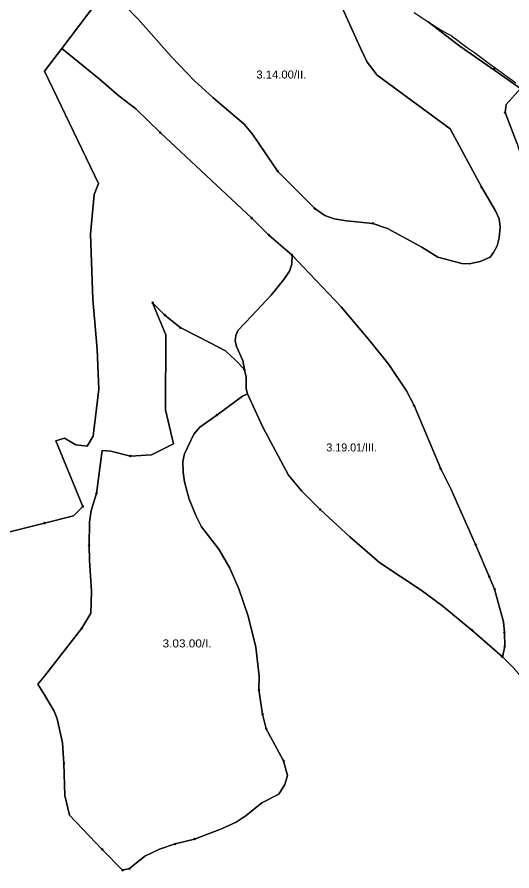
# Model space of a CAD drawing. Extents: x -650455 to -642254, y -1075222 to -1066610.
# Drawn here: x -645034 to -644416, y -1073102 to -1072036 of the extents above; entities that cross this region are included whole.
import ezdxf
from ezdxf.enums import TextEntityAlignment as Align

# ---------------------------------------------------------------- set-up
doc = ezdxf.new("R2010")
doc.units = 0
doc.header["$LTSCALE"] = 4
doc.header["$PDMODE"] = 32
doc.header["$PDSIZE"] = 2
for name, color, linetype, lineweight in [('1', 7, 'Continuous', 25), ('11', 7, 'Continuous', 13), ('12', 7, 'Continuous', 13), ('13', 7, 'Continuous', 13), ('14', 7, 'Continuous', 13)]:
    doc.layers.add(name, color=color, linetype=linetype, lineweight=lineweight)
doc.layers.add('2', color=7, linetype='Continuous')

msp = doc.modelspace()

# ---------------------------------------------------------------- linework, layer by layer
at = {"layer": '1'}
for points in [[(-644841.196, -1072085.989), (-644882.287, -1072039.303), (-644920.668, -1072000), (-644846.005, -1071899.418), (-644841.808, -1071890.5), (-644840.584, -1071879.659), (-644841.109, -1071869.867), (-644842.508, -1071858.851), (-644848.802, -1071841.89), (-644852.999, -1071832.972), (-644858.507, -1071824.054), (-644814.968, -1071847.135), (-644781.395, -1071868.992)], [(-644431.857, -1072311.904), (-644430.633, -1072298.615), (-644431.682, -1072288.473), (-644436.403, -1072278.331), (-644453.627, -1072249.305), (-644492.882, -1072176.04), (-644584.42, -1072108.721), (-644596.572, -1072092.634), (-644604.965, -1072074.973), (-644630.931, -1072017.97), (-644644.606, -1072000), (-644652.089, -1071990.168), (-644682.776, -1071960.792), (-644705.508, -1071942.607), (-644747.386, -1071912.357), (-644761.374, -1071900.641), (-644769.942, -1071891.374), (-644776.237, -1071882.107), (-644781.395, -1071868.992), (-644763.822, -1071881.057), (-644761.199, -1071879.659), (-644742.849, -1071890.721)], [(-644923.589, -1072003.101), (-644978.202, -1072075.468), (-645000, -1072103.795), (-644932.308, -1072244.028), (-644938, -1072258.001), (-644942.5, -1072307.5), (-644939.5, -1072388.5), (-644934, -1072451.501)], [(-644504.788, -1072600.507), (-644538.098, -1072521.472), (-644547.541, -1072502.937), (-644569.835, -1072470.239), (-644593.265, -1072440.689), (-644629.198, -1072398.199), (-644676.672, -1072348.015), (-644690.563, -1072333.557), (-644719.414, -1072308.552), (-644741.009, -1072287.394), (-644855.103, -1072180.732), (-644885.79, -1072150.832), (-644907.123, -1072134.745), (-644931.428, -1072113.412), (-644978.202, -1072075.468), (-644923.589, -1072003.101)], [(-644920.668, -1072000), (-644882.287, -1072039.303), (-644841.196, -1072085.989), (-644812.607, -1072115.89), (-644789.351, -1072136.698), (-644750.62, -1072169.92), (-644740.129, -1072182.51), (-644708.393, -1072229.022), (-644684.088, -1072253.327), (-644662.318, -1072275.534), (-644649.728, -1072283.927), (-644637.838, -1072288.298), (-644622.451, -1072290.921), (-644589.753, -1072293.893), (-644571.218, -1072300.538), (-644528.64, -1072323.619), (-644508.357, -1072336.209), (-644478.457, -1072343.902), (-644469.539, -1072344.602), (-644455.463, -1072341.629), (-644443.223, -1072336.034), (-644439.026, -1072330.264), (-644434.305, -1072322.045), (-644431.857, -1072311.904)], [(-644630.931, -1072017.97), (-644604.965, -1072074.973), (-644596.572, -1072092.634), (-644584.42, -1072108.721), (-644492.882, -1072176.04), (-644453.627, -1072249.305), (-644436.403, -1072278.331), (-644431.682, -1072288.473), (-644430.633, -1072298.615), (-644431.857, -1072311.904), (-644434.305, -1072322.045), (-644439.026, -1072330.264), (-644443.223, -1072336.034), (-644455.463, -1072341.629), (-644469.539, -1072344.602), (-644478.457, -1072343.902), (-644508.357, -1072336.209), (-644528.64, -1072323.619), (-644571.218, -1072300.538), (-644589.753, -1072293.893), (-644622.451, -1072290.921), (-644637.838, -1072288.298), (-644649.728, -1072283.927), (-644662.318, -1072275.534), (-644684.088, -1072253.327), (-644708.393, -1072229.022), (-644740.129, -1072182.51), (-644750.62, -1072169.92), (-644789.351, -1072136.698), (-644812.607, -1072115.89), (-644841.196, -1072085.989)], [(-644538.207, -1072030.496), (-644520.385, -1072042.196), (-644480.817, -1072072.875), (-644437.149, -1072103.18), (-644405.404, -1072125.733), (-644423.152, -1072145.492), (-644424.551, -1072155.634), (-644409.426, -1072194.802), (-644395.962, -1072238.516), (-644382.411, -1072266.143), (-644377.69, -1072283.279), (-644368.51, -1072344.479), (-644363.526, -1072367.91), (-644357.056, -1072388.717), (-644349.887, -1072398.859), (-644340.095, -1072405.329), (-644329.079, -1072409.525), (-644322.085, -1072408.476), (-644311.769, -1072403.231), (-644304.425, -1072396.061), (-644301.277, -1072389.242), (-644299.529, -1072379.975), (-644298.392, -1072369.308), (-644286.239, -1072437.852)], [(-645051.292, -1072681.171), (-645000, -1072668.218), (-644963.5, -1072659), (-644952, -1072647.5), (-644985.633, -1072565.416), (-644974.792, -1072562.094), (-644960.629, -1072570.487), (-644946.5, -1072572.001), (-644939, -1072559.5), (-644932, -1072501.001), (-644934, -1072451.501), (-644939.5, -1072388.5), (-644942.5, -1072307.5), (-644938, -1072258.001), (-644932.308, -1072244.028), (-645000, -1072103.795), (-644978.202, -1072075.468), (-644931.428, -1072113.412), (-644907.123, -1072134.745), (-644885.79, -1072150.832), (-644855.103, -1072180.732), (-644741.009, -1072287.394), (-644719.414, -1072308.552), (-644690.563, -1072333.557)], [(-644405.404, -1072125.733), (-644437.149, -1072103.18), (-644438.697, -1072098.552), (-644410.923, -1072118.41)], [(-644409.426, -1072194.802), (-644424.551, -1072155.634), (-644423.152, -1072145.492), (-644405.404, -1072125.733)], [(-644690.563, -1072333.557), (-644690.913, -1072344.747), (-644693.885, -1072353.49), (-644700.967, -1072363.982), (-644716.704, -1072383.566), (-644741.009, -1072409.444), (-644758.407, -1072427.629), (-644761.03, -1072433.924), (-644761.555, -1072440.569), (-644759.806, -1072447.563), (-644752.2, -1072465.224), (-644750.102, -1072476.589), (-644761.118, -1072464.699), (-644773.882, -1072453.158), (-644791.892, -1072443.716), (-644830.186, -1072424.132), (-644849.42, -1072408.395), (-644864.72, -1072393.008), (-644848.109, -1072433.225), (-644848.721, -1072526.773), (-644838.492, -1072569.088), (-644866.119, -1072582.902), (-644892.522, -1072584.476), (-644917.177, -1072578.356), (-644927.668, -1072577.656), (-644934.935, -1072631.107), (-644941.579, -1072652.265), (-644943.59, -1072666.953), (-644944.115, -1072695.979), (-644943.415, -1072715.038), (-644941.055, -1072753.157), (-644941.841, -1072780.784), (-644953.207, -1072799.494), (-645000, -1072859.198), (-645008.025, -1072869.436), (-645000, -1072882.662), (-644987.654, -1072903.009), (-644983.807, -1072912.451), (-644977.337, -1072942.526), (-644975.501, -1072968.405)], [(-644968.595, -1073032.752), (-644974.54, -1073008.447), (-644975.501, -1072968.405), (-644977.337, -1072942.526), (-644983.807, -1072912.451), (-644987.654, -1072903.009), (-645000, -1072882.662), (-645008.025, -1072869.436), (-645000, -1072859.198), (-644953.207, -1072799.494), (-644941.841, -1072780.784), (-644941.055, -1072753.157), (-644943.415, -1072715.038), (-644944.115, -1072695.979), (-644943.59, -1072666.953), (-644941.579, -1072652.265), (-644934.935, -1072631.107), (-644927.668, -1072577.656), (-644917.177, -1072578.356), (-644892.522, -1072584.476), (-644866.119, -1072582.902), (-644838.492, -1072569.088), (-644848.721, -1072526.773), (-644848.109, -1072433.225), (-644864.72, -1072393.008), (-644849.42, -1072408.395), (-644830.186, -1072424.132), (-644791.892, -1072443.716), (-644773.882, -1072453.158), (-644761.118, -1072464.699), (-644750.102, -1072476.589)], [(-644934, -1072451.501), (-644932, -1072501.001), (-644939, -1072559.5), (-644946.5, -1072572.001), (-644960.629, -1072570.487), (-644974.792, -1072562.094), (-644985.633, -1072565.416), (-644952, -1072647.5), (-644963.5, -1072659), (-645000, -1072668.218), (-645051.292, -1072681.171)], [(-644750.102, -1072476.589), (-644747.829, -1072486.556), (-644748.004, -1072500.37), (-644746.255, -1072506.665), (-644752.385, -1072509.582), (-644784.471, -1072533.362), (-644805.629, -1072548.4), (-644813.322, -1072556.968), (-644825.037, -1072581.623), (-644827.136, -1072591.24), (-644826.699, -1072604.529), (-644824.775, -1072616.769), (-644819.18, -1072638.101), (-644810.35, -1072659.609), (-644803.53, -1072672.723), (-644782.198, -1072700.525), (-644768.122, -1072724.481), (-644757.106, -1072750.184), (-644745.478, -1072784.281), (-644736.036, -1072822.925), (-644731.752, -1072859.47), (-644731.926, -1072876.256), (-644727.468, -1072906.856), (-644722.921, -1072924.866), (-644701.152, -1072965.083), (-644696.256, -1072983.443), (-644699.753, -1072994.634), (-644707.097, -1073006.699), (-644728.342, -1073017.54), (-644747.926, -1073033.102), (-644760.341, -1073041.67), (-644778.7, -1073050.063), (-644812.273, -1073062.653), (-644836.491, -1073068.773), (-644856.074, -1073075.417), (-644874.609, -1073083.985), (-644893.669, -1073099.547), (-644902.412, -1073101.471), (-644927.591, -1073075.592), (-644968.595, -1073032.752)], [(-644975.501, -1072968.405), (-644974.54, -1073008.447), (-644968.595, -1073032.752), (-644927.591, -1073075.592), (-644902.412, -1073101.471), (-644893.669, -1073099.547), (-644874.609, -1073083.985), (-644856.074, -1073075.417), (-644836.491, -1073068.773), (-644812.273, -1073062.653), (-644778.7, -1073050.063), (-644760.341, -1073041.67), (-644747.926, -1073033.102), (-644728.342, -1073017.54), (-644707.097, -1073006.699), (-644699.753, -1072994.634), (-644696.256, -1072983.443), (-644701.152, -1072965.083), (-644722.921, -1072924.866), (-644727.468, -1072906.856), (-644731.926, -1072876.256), (-644731.752, -1072859.47), (-644736.036, -1072822.925), (-644745.478, -1072784.281), (-644757.106, -1072750.184), (-644768.122, -1072724.481), (-644782.198, -1072700.525), (-644803.53, -1072672.723), (-644810.35, -1072659.609), (-644819.18, -1072638.101), (-644824.775, -1072616.769), (-644826.699, -1072604.529), (-644827.136, -1072591.24), (-644825.037, -1072581.623), (-644813.322, -1072556.968), (-644805.629, -1072548.4), (-644784.471, -1072533.362), (-644752.385, -1072509.582), (-644746.255, -1072506.665), (-644727.03, -1072548.225)], [(-644727.03, -1072548.225), (-644695.119, -1072608.201), (-644678.508, -1072628.484), (-644655.514, -1072651.216), (-644618.27, -1072685.138), (-644580.763, -1072717.661), (-644529.268, -1072751.758), (-644502.165, -1072771.867), (-644465.97, -1072801.767), (-644427.764, -1072835.165), (-644413.997, -1072848.687)], [(-644413.997, -1072848.687), (-644427.764, -1072835.165), (-644424.966, -1072822.225), (-644425.316, -1072804.914), (-644426.54, -1072791.45), (-644437.556, -1072750.534), (-644444.375, -1072734.797), (-644461.249, -1072695.105), (-644492.286, -1072625.512), (-644504.788, -1072600.507)]]:
    msp.add_lwpolyline(points, dxfattribs=at)
for points in [[(-644438.697, -1072098.552), (-644437.149, -1072103.18), (-644480.817, -1072072.875), (-644520.385, -1072042.196), (-644505.751, -1072051.804), (-644497.002, -1072057.025), (-644493.333, -1072058.718), (-644492.204, -1072058.859), (-644491.922, -1072059.566), (-644471.32, -1072074.806), (-644462.853, -1072080.592), (-644441.121, -1072096.818)], [(-644427.764, -1072835.165), (-644465.97, -1072801.767), (-644502.165, -1072771.867), (-644529.268, -1072751.758), (-644580.763, -1072717.661), (-644618.27, -1072685.138), (-644655.514, -1072651.216), (-644678.508, -1072628.484), (-644695.119, -1072608.201), (-644727.03, -1072548.225), (-644746.255, -1072506.665), (-644748.004, -1072500.37), (-644747.829, -1072486.556), (-644750.102, -1072476.589), (-644752.2, -1072465.224), (-644759.806, -1072447.563), (-644761.555, -1072440.569), (-644761.03, -1072433.924), (-644758.407, -1072427.629), (-644741.009, -1072409.444), (-644716.704, -1072383.566), (-644700.967, -1072363.982), (-644693.885, -1072353.49), (-644690.913, -1072344.747), (-644690.563, -1072333.557), (-644676.672, -1072348.015), (-644629.198, -1072398.199), (-644593.265, -1072440.689), (-644569.835, -1072470.239), (-644547.541, -1072502.937), (-644538.098, -1072521.472), (-644504.788, -1072600.507), (-644492.286, -1072625.512), (-644461.249, -1072695.105), (-644444.375, -1072734.797), (-644437.556, -1072750.534), (-644426.54, -1072791.45), (-644425.316, -1072804.914), (-644424.966, -1072822.225)]]:
    msp.add_lwpolyline(points, close=True, dxfattribs=at)
at = {"layer": '11'}
for p, q in [((-644727.468, -1072906.856), (-644731.926, -1072876.256)), ((-644722.921, -1072924.866), (-644727.468, -1072906.856)), ((-644968.595, -1073032.752), (-644927.591, -1073075.592)), ((-644927.591, -1073075.592), (-644902.412, -1073101.471))]:
    msp.add_line(p, q, dxfattribs=at)
for points in [[(-645000, -1072668.218), (-644963.5, -1072659), (-644952, -1072647.5), (-644985.633, -1072565.416), (-644974.792, -1072562.094), (-644960.629, -1072570.487), (-644946.5, -1072572.001), (-644939, -1072559.5), (-644932, -1072501.001), (-644934, -1072451.501), (-644939.5, -1072388.5), (-644942.5, -1072307.5), (-644938, -1072258.001), (-644932.308, -1072244.028), (-645000, -1072103.795), (-644978.202, -1072075.468), (-644923.589, -1072003.101), (-644924, -1072000)], [(-644410.923, -1072118.41), (-644438.697, -1072098.552), (-644437.149, -1072103.18), (-644405.404, -1072125.733)], [(-645232, -1072393.5), (-645239, -1072447.501), (-645252.5, -1072519.501), (-645249.5, -1072546.5), (-645229.5, -1072578), (-645192.5, -1072623), (-645125, -1072686.501), (-645107.317, -1072702.887), (-645051.292, -1072681.171), (-645000, -1072668.218)], [(-644864.72, -1072393.008), (-644848.109, -1072433.225), (-644848.721, -1072526.773), (-644838.492, -1072569.088), (-644866.119, -1072582.902), (-644892.522, -1072584.476), (-644917.177, -1072578.356), (-644927.668, -1072577.656), (-644934.935, -1072631.107), (-644941.579, -1072652.265), (-644943.59, -1072666.953), (-644944.115, -1072695.979), (-644943.415, -1072715.038), (-644941.055, -1072753.157), (-644941.841, -1072780.784), (-644953.207, -1072799.494), (-645000, -1072859.198), (-645008.025, -1072869.436), (-645000, -1072882.662), (-644987.654, -1072903.009), (-644983.807, -1072912.451), (-644977.337, -1072942.526), (-644975.501, -1072968.405), (-644974.54, -1073008.447), (-644968.595, -1073032.752)], [(-644731.926, -1072876.256), (-644731.752, -1072859.47), (-644736.036, -1072822.925), (-644745.478, -1072784.281), (-644757.106, -1072750.184), (-644768.122, -1072724.481), (-644782.198, -1072700.525), (-644803.53, -1072672.723), (-644810.35, -1072659.609), (-644819.18, -1072638.101), (-644824.775, -1072616.769), (-644826.699, -1072604.529), (-644827.136, -1072591.24), (-644825.037, -1072581.623), (-644813.322, -1072556.968), (-644805.629, -1072548.4), (-644784.471, -1072533.362), (-644752.385, -1072509.582), (-644746.255, -1072506.665), (-644748.004, -1072500.37), (-644747.829, -1072486.556), (-644750.102, -1072476.589), (-644761.118, -1072464.699), (-644773.882, -1072453.158), (-644791.892, -1072443.716), (-644830.186, -1072424.132), (-644849.42, -1072408.395), (-644864.72, -1072393.008)], [(-644812.273, -1073062.653), (-644778.7, -1073050.063), (-644760.341, -1073041.67), (-644747.926, -1073033.102), (-644728.342, -1073017.54), (-644707.097, -1073006.699), (-644699.753, -1072994.634), (-644696.256, -1072983.443), (-644701.152, -1072965.083), (-644722.921, -1072924.866)], [(-644902.412, -1073101.471), (-644893.669, -1073099.547), (-644874.609, -1073083.985), (-644856.074, -1073075.417), (-644836.491, -1073068.773), (-644812.273, -1073062.653)]]:
    msp.add_lwpolyline(points, dxfattribs=at)
for p in [(-644864.72, -1072393.008), (-645000, -1072668.218), (-644731.926, -1072876.256), (-644727.468, -1072906.856), (-644722.921, -1072924.866), (-644812.273, -1073062.653), (-644927.591, -1073075.592), (-644902.412, -1073101.471)]:
    msp.add_point(p, dxfattribs=at)
at = {"layer": '12'}
for points in [[(-644920.668, -1072000), (-644882.287, -1072039.303), (-644841.196, -1072085.989), (-644812.607, -1072115.89), (-644789.351, -1072136.698), (-644750.62, -1072169.92), (-644740.129, -1072182.51), (-644708.393, -1072229.022)], [(-644453.627, -1072249.305), (-644492.882, -1072176.04), (-644584.42, -1072108.721), (-644596.572, -1072092.634), (-644604.965, -1072074.973), (-644630.931, -1072017.97)], [(-644708.393, -1072229.022), (-644684.088, -1072253.327), (-644662.318, -1072275.534), (-644649.728, -1072283.927), (-644637.838, -1072288.298), (-644622.451, -1072290.921), (-644589.753, -1072293.893)], [(-644589.753, -1072293.893), (-644571.218, -1072300.538), (-644528.64, -1072323.619), (-644508.357, -1072336.209), (-644478.457, -1072343.902), (-644469.539, -1072344.602), (-644455.463, -1072341.629), (-644443.223, -1072336.034), (-644439.026, -1072330.264), (-644434.305, -1072322.045), (-644431.857, -1072311.904), (-644430.633, -1072298.615), (-644431.682, -1072288.473), (-644436.403, -1072278.331), (-644453.627, -1072249.305)]]:
    msp.add_lwpolyline(points, dxfattribs=at)
for p in [(-644708.393, -1072229.022), (-644453.627, -1072249.305), (-644589.753, -1072293.893)]:
    msp.add_point(p, dxfattribs=at)
at = {"layer": '13'}
for p, q in [((-644741.009, -1072287.394), (-644855.103, -1072180.732)), ((-644849.42, -1072408.395), (-644830.186, -1072424.132)), ((-644444.375, -1072734.797), (-644437.556, -1072750.534)), ((-644427.764, -1072835.165), (-644465.97, -1072801.767))]:
    msp.add_line(p, q, dxfattribs=at)
for points in [[(-644662.318, -1072275.534), (-644684.088, -1072253.327), (-644708.393, -1072229.022), (-644740.129, -1072182.51), (-644750.62, -1072169.92), (-644789.351, -1072136.698), (-644812.607, -1072115.89), (-644841.196, -1072085.989), (-644882.287, -1072039.303), (-644920.668, -1072000), (-644923.589, -1072003.101), (-644978.202, -1072075.468), (-644931.428, -1072113.412), (-644907.123, -1072134.745), (-644885.79, -1072150.832), (-644855.103, -1072180.732), (-644741.009, -1072287.394), (-644719.414, -1072308.552)], [(-644630.931, -1072017.97), (-644604.965, -1072074.973), (-644596.572, -1072092.634), (-644584.42, -1072108.721), (-644492.882, -1072176.04), (-644453.627, -1072249.305)], [(-644424.551, -1072155.634), (-644423.152, -1072145.492), (-644405.404, -1072125.733), (-644437.149, -1072103.18), (-644480.817, -1072072.875), (-644520.385, -1072042.196), (-644538.207, -1072030.496)], [(-644855.103, -1072180.732), (-644885.79, -1072150.832), (-644907.123, -1072134.745), (-644931.428, -1072113.412), (-644978.202, -1072075.468), (-645000, -1072103.795), (-644932.308, -1072244.028), (-644938, -1072258.001), (-644942.5, -1072307.5), (-644939.5, -1072388.5), (-644934, -1072451.501), (-644932, -1072501.001), (-644939, -1072559.5), (-644946.5, -1072572.001), (-644960.629, -1072570.487), (-644974.792, -1072562.094), (-644985.633, -1072565.416), (-644952, -1072647.5)], [(-644409.426, -1072194.802), (-644424.551, -1072155.634)], [(-644453.627, -1072249.305), (-644436.403, -1072278.331), (-644431.682, -1072288.473), (-644430.633, -1072298.615), (-644431.857, -1072311.904), (-644434.305, -1072322.045), (-644439.026, -1072330.264), (-644443.223, -1072336.034), (-644455.463, -1072341.629), (-644469.539, -1072344.602), (-644478.457, -1072343.902), (-644508.357, -1072336.209), (-644528.64, -1072323.619), (-644571.218, -1072300.538), (-644589.753, -1072293.893), (-644622.451, -1072290.921), (-644637.838, -1072288.298), (-644649.728, -1072283.927), (-644662.318, -1072275.534)], [(-644690.563, -1072333.557), (-644719.414, -1072308.552), (-644741.009, -1072287.394)], [(-644719.414, -1072308.552), (-644690.563, -1072333.557), (-644676.672, -1072348.015), (-644629.198, -1072398.199), (-644593.265, -1072440.689), (-644569.835, -1072470.239), (-644547.541, -1072502.937), (-644538.098, -1072521.472)], [(-644504.788, -1072600.507), (-644538.098, -1072521.472), (-644547.541, -1072502.937), (-644569.835, -1072470.239), (-644593.265, -1072440.689), (-644629.198, -1072398.199), (-644676.672, -1072348.015), (-644690.563, -1072333.557), (-644690.913, -1072344.747), (-644693.885, -1072353.49), (-644700.967, -1072363.982), (-644716.704, -1072383.566), (-644741.009, -1072409.444), (-644758.407, -1072427.629), (-644761.03, -1072433.924), (-644761.555, -1072440.569), (-644759.806, -1072447.563), (-644752.2, -1072465.224), (-644750.102, -1072476.589), (-644747.829, -1072486.556), (-644748.004, -1072500.37), (-644746.255, -1072506.665), (-644727.03, -1072548.225), (-644695.119, -1072608.201), (-644678.508, -1072628.484), (-644655.514, -1072651.216)], [(-644750.102, -1072476.589), (-644752.2, -1072465.224), (-644759.806, -1072447.563), (-644761.555, -1072440.569), (-644761.03, -1072433.924), (-644758.407, -1072427.629), (-644741.009, -1072409.444), (-644716.704, -1072383.566), (-644700.967, -1072363.982), (-644693.885, -1072353.49), (-644690.913, -1072344.747), (-644690.563, -1072333.557)], [(-644892.522, -1072584.476), (-644866.119, -1072582.902), (-644838.492, -1072569.088), (-644848.721, -1072526.773), (-644848.109, -1072433.225), (-644864.72, -1072393.008), (-644849.42, -1072408.395)], [(-644830.186, -1072424.132), (-644791.892, -1072443.716), (-644773.882, -1072453.158), (-644761.118, -1072464.699), (-644750.102, -1072476.589)], [(-644655.514, -1072651.216), (-644678.508, -1072628.484), (-644695.119, -1072608.201), (-644727.03, -1072548.225), (-644746.255, -1072506.665), (-644752.385, -1072509.582), (-644784.471, -1072533.362)], [(-644538.098, -1072521.472), (-644504.788, -1072600.507), (-644492.286, -1072625.512), (-644461.249, -1072695.105), (-644444.375, -1072734.797)], [(-644784.471, -1072533.362), (-644805.629, -1072548.4), (-644813.322, -1072556.968), (-644825.037, -1072581.623), (-644827.136, -1072591.24), (-644826.699, -1072604.529), (-644824.775, -1072616.769), (-644819.18, -1072638.101), (-644810.35, -1072659.609), (-644803.53, -1072672.723), (-644782.198, -1072700.525), (-644768.122, -1072724.481), (-644757.106, -1072750.184), (-644745.478, -1072784.281), (-644736.036, -1072822.925), (-644731.752, -1072859.47), (-644731.926, -1072876.256)], [(-644934.935, -1072631.107), (-644927.668, -1072577.656), (-644917.177, -1072578.356), (-644892.522, -1072584.476)], [(-644461.249, -1072695.105), (-644492.286, -1072625.512), (-644504.788, -1072600.507)], [(-644944.115, -1072695.979), (-644943.59, -1072666.953), (-644941.579, -1072652.265), (-644934.935, -1072631.107)], [(-644952, -1072647.5), (-644963.5, -1072659), (-645000, -1072668.218), (-645051.292, -1072681.171)], [(-644655.514, -1072651.216), (-644618.27, -1072685.138), (-644580.763, -1072717.661), (-644529.268, -1072751.758), (-644502.165, -1072771.867), (-644465.97, -1072801.767), (-644427.764, -1072835.165), (-644424.966, -1072822.225), (-644425.316, -1072804.914)], [(-644465.97, -1072801.767), (-644502.165, -1072771.867), (-644529.268, -1072751.758), (-644580.763, -1072717.661), (-644618.27, -1072685.138), (-644655.514, -1072651.216)], [(-644953.207, -1072799.494), (-644941.841, -1072780.784), (-644941.055, -1072753.157), (-644943.415, -1072715.038), (-644944.115, -1072695.979)], [(-644425.316, -1072804.914), (-644426.54, -1072791.45), (-644437.556, -1072750.534), (-644444.375, -1072734.797), (-644461.249, -1072695.105)], [(-644437.556, -1072750.534), (-644426.54, -1072791.45), (-644425.316, -1072804.914), (-644424.966, -1072822.225)], [(-644975.501, -1072968.405), (-644977.337, -1072942.526), (-644983.807, -1072912.451), (-644987.654, -1072903.009), (-645000, -1072882.662), (-645008.025, -1072869.436), (-645000, -1072859.198), (-644953.207, -1072799.494)], [(-644424.966, -1072822.225), (-644427.764, -1072835.165), (-644413.997, -1072848.687)], [(-644332.951, -1072950.978), (-644384.621, -1072887.855), (-644400.183, -1072865.124), (-644413.997, -1072848.687), (-644427.764, -1072835.165)], [(-644731.926, -1072876.256), (-644727.468, -1072906.856), (-644722.921, -1072924.866), (-644701.152, -1072965.083)], [(-644893.669, -1073099.547), (-644902.412, -1073101.471), (-644927.591, -1073075.592), (-644968.595, -1073032.752), (-644974.54, -1073008.447), (-644975.501, -1072968.405)], [(-644701.152, -1072965.083), (-644696.256, -1072983.443), (-644699.753, -1072994.634), (-644707.097, -1073006.699), (-644728.342, -1073017.54), (-644747.926, -1073033.102), (-644760.341, -1073041.67), (-644778.7, -1073050.063), (-644812.273, -1073062.653), (-644836.491, -1073068.773)], [(-644836.491, -1073068.773), (-644856.074, -1073075.417), (-644874.609, -1073083.985), (-644893.669, -1073099.547)]]:
    msp.add_lwpolyline(points, dxfattribs=at)
for p in [(-644424.551, -1072155.634), (-644855.103, -1072180.732), (-644662.318, -1072275.534), (-644741.009, -1072287.394), (-644719.414, -1072308.552), (-644690.563, -1072333.557), (-644849.42, -1072408.395), (-644830.186, -1072424.132), (-644750.102, -1072476.589), (-644538.098, -1072521.472), (-644784.471, -1072533.362), (-644892.522, -1072584.476), (-644504.788, -1072600.507), (-644934.935, -1072631.107), (-644952, -1072647.5), (-644655.514, -1072651.216), (-644944.115, -1072695.979), (-644461.249, -1072695.105), (-644444.375, -1072734.797), (-644437.556, -1072750.534), (-644953.207, -1072799.494), (-644465.97, -1072801.767), (-644425.316, -1072804.914), (-644424.966, -1072822.225), (-644427.764, -1072835.165), (-644731.926, -1072876.256), (-644975.501, -1072968.405), (-644701.152, -1072965.083), (-644836.491, -1073068.773), (-644893.669, -1073099.547)]:
    msp.add_point(p, dxfattribs=at)
at = {"layer": '14'}
msp.add_lwpolyline([(-644405.404, -1072125.733), (-644423.152, -1072145.492), (-644424.551, -1072155.634), (-644409.426, -1072194.802)], dxfattribs=at)

# ---------------------------------------------------------------- texts
at = {"layer": '2'}
for s, width, p in [('3.14.00/II.', 1.05, (-644703.938, -1072113.086)), ('3.03.00/I.', 1.1, (-644821.649, -1072823.414))]:
    msp.add_text(s, height=10, dxfattribs=dict(at, width=width)).set_placement(p, align=Align.CENTER)
msp.add_text('3.19.01/III.', height=10, dxfattribs=at).set_placement((-644616.149, -1072578.713), align=Align.CENTER)

doc.saveas('drawing.dxf')
